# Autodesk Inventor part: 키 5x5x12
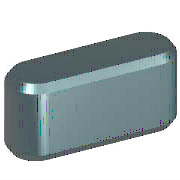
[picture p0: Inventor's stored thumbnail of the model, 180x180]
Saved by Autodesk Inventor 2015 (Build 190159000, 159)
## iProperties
IsCustomPart: 1
Created: 2012-02
Part Number: 키 5x5x12
Material: 강철, 연강
Description: 키 및 해당 키홈
Document SubType Name: Modeling
Standard: KS B 1311
Designer: mduedu
Standards Organization: KS
Language: ko-KR
Size Designation: 5 x 5 x 12
Categories: <MemberInstance><Categories><Category DisplayName="샤프트 부품" InternalName="7f7aeb1f-a693-4053-b835-cee3144e0d98" Mnemonic="SHFT"><Category DisplayName="키" Interna
Density: 1 g/cm^3
Appearance: 노란색
Author: mduedu
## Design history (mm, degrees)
workplane "Work Plane1"
workplane "Work Plane2"
sketch "스케치1"
  geometry: L1 (2.5, 2.5)-(9.5, 2.5); L2 (9.5, -2.5)-(2.5, -2.5); L3 (0, 9.4)-(0, -7.4) reference; L4 (-5, 0)-(30, 0) reference; L5 (12, 0)-(12, 7); A1 r 2.5 centre (2.5, 0) between (2.5, 2.5) and (2.5, -2.5); A2 r 2.5 centre (9.5, 0) between (9.5, -2.5) and (9.5, 2.5)
  constraints: 6 end point, 5 point on circle, 4 tangent, 3 point on line, 2 centre point, 1 horizontal, 1 parallel, 1 perpendicular
  dimensions: "d0" = 2.5 radius of A1 (= 0.5 x PB); "d13" = 2.5 radius of A2 (= 0.5 x PB); "d14" = 12 distance between parallel lines of L5 L3 (= NLG)
extrude "본체1" new body sketch "스케치1" taper "d3" = 0 deg; stored distance "d4" = 10
workplane "Work Plane3"
body "Solid1"
chamfer "모따기1" distance "d8" = 0.4 (= PHH); stored, may be unused: second distance "d9" = 0.4 (= PHH), angle "d15" = 45 deg
other parameters: "d1" = -3 (= -PNT), "d2" = 2 (= PH - PNT), "NLG" = 12 [user parameter; used in 3 equation terms], "PB" = 5 [user parameter; used in 2 equation terms], "PNT" = 3 [user parameter; used in 2 equation terms], "PH" = 5 [user parameter; used in 1 equation term], "PHH" = 0.4 [user parameter; used in 2 equation terms], "d10" = 0, "d16" = 0, "d17" = 0, "d18" = 0, "WDMIN" = 12 [user parameter], "PLB2" = 12 (= NLG) [user parameter], "WDMAX" = 17 [user parameter], "PLB1" = 12 (= NLG) [user parameter], "RR" = 0.16 [user parameter], "PUEB" = 2.3 [user parameter]
